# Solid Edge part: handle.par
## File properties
Title: Handle
Author: Robert a Rhodes jr
Template: Normal.par
Last saved by: TIET
Revision: 10
Application: Solid Edge
Accuracy: 0.99
Material: aluminum
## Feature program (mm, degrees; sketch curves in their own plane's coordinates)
sketch for "unnamed RevolvedProtrusion 1" plane through (0, 0, 0) normal (0, -1, 0) x-axis (1, 0, 0)
  line (-87.868, 0.2971) -> (-87.868, -4)
  line (-87.868, -4) -> (-79.868, -4)
  line (-79.868, -4) -> (-79.868, -5)
  line (-79.868, -5) -> (76.132, -5)
  line (76.132, -5) -> (76.132, -4)
  line (76.132, -4) -> (84.132, -4)
  line (84.132, -4) -> (84.132, 0.2971)
revolve "unnamed RevolvedProtrusion 1" add finite 360 deg about sketch line (-87.868, 0.2971) -> (84.132, 0.2971)
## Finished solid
Body 1: solid body, 7 faces, 6 edges, 0 vertices.
  Faces by surface: plane 4, cylinder 3
  Edges by curve: circle 6
Bounding box of the edges (mm): 172.000 x 10.594 x 10.594, from (-87.868, -5.2971, -5) to (84.132, 5.2971, 5.5941).
Cylindrical faces by radius (mm): R4.2971 x2, R5.2971 x1
Planar faces by outward normal: +x 2, -x 2
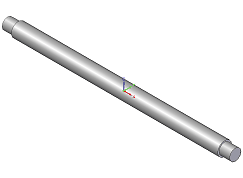
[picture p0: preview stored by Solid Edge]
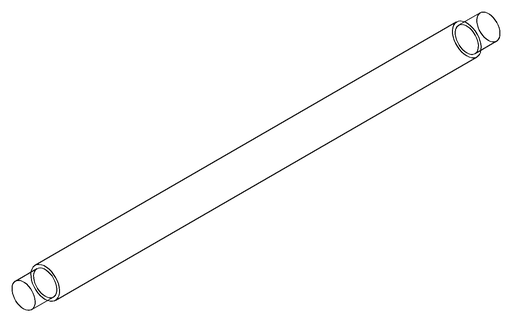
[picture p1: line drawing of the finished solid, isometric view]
